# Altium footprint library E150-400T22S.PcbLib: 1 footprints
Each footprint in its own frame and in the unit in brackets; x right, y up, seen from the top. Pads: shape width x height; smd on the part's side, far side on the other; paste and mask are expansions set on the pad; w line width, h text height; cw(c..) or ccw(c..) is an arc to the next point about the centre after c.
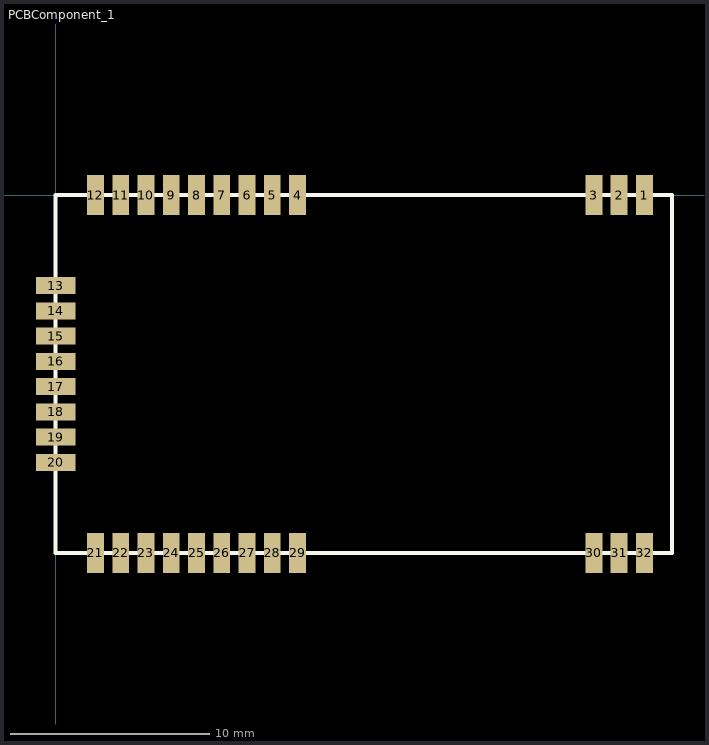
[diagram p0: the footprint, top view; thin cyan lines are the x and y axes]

## PCBComponent_1 [mm]
pads (32):
  rect 0.85x2 smd: 1(29.6,0) 2(28.33,0) 3(27.06,0) 4(12.16,0) 5(10.89,0) 6(9.62,0) 7(8.35,0) 8(7.08,0) 9(5.81,0) 10(4.54,0) 11(3.27,0) 12(2,0) 21(2,-18) 22(3.27,-18) 23(4.54,-18) 24(5.81,-18) 25(7.08,-18) 26(8.35,-18) 27(9.62,-18) 28(10.89,-18) 29(12.16,-18) 30(27.06,-18) 31(28.33,-18) 32(29.6,-18)
  rect 2x0.85 smd: 13(0,-4.555) 14(0,-5.825) 15(0,-7.095) 16(0,-8.365) 17(0,-9.635) 18(0,-10.905) 19(0,-12.175) 20(0,-13.445)
Top Overlay:
  lines w0.2: 0,-18 0,0 31,0 31,-18 0,-18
